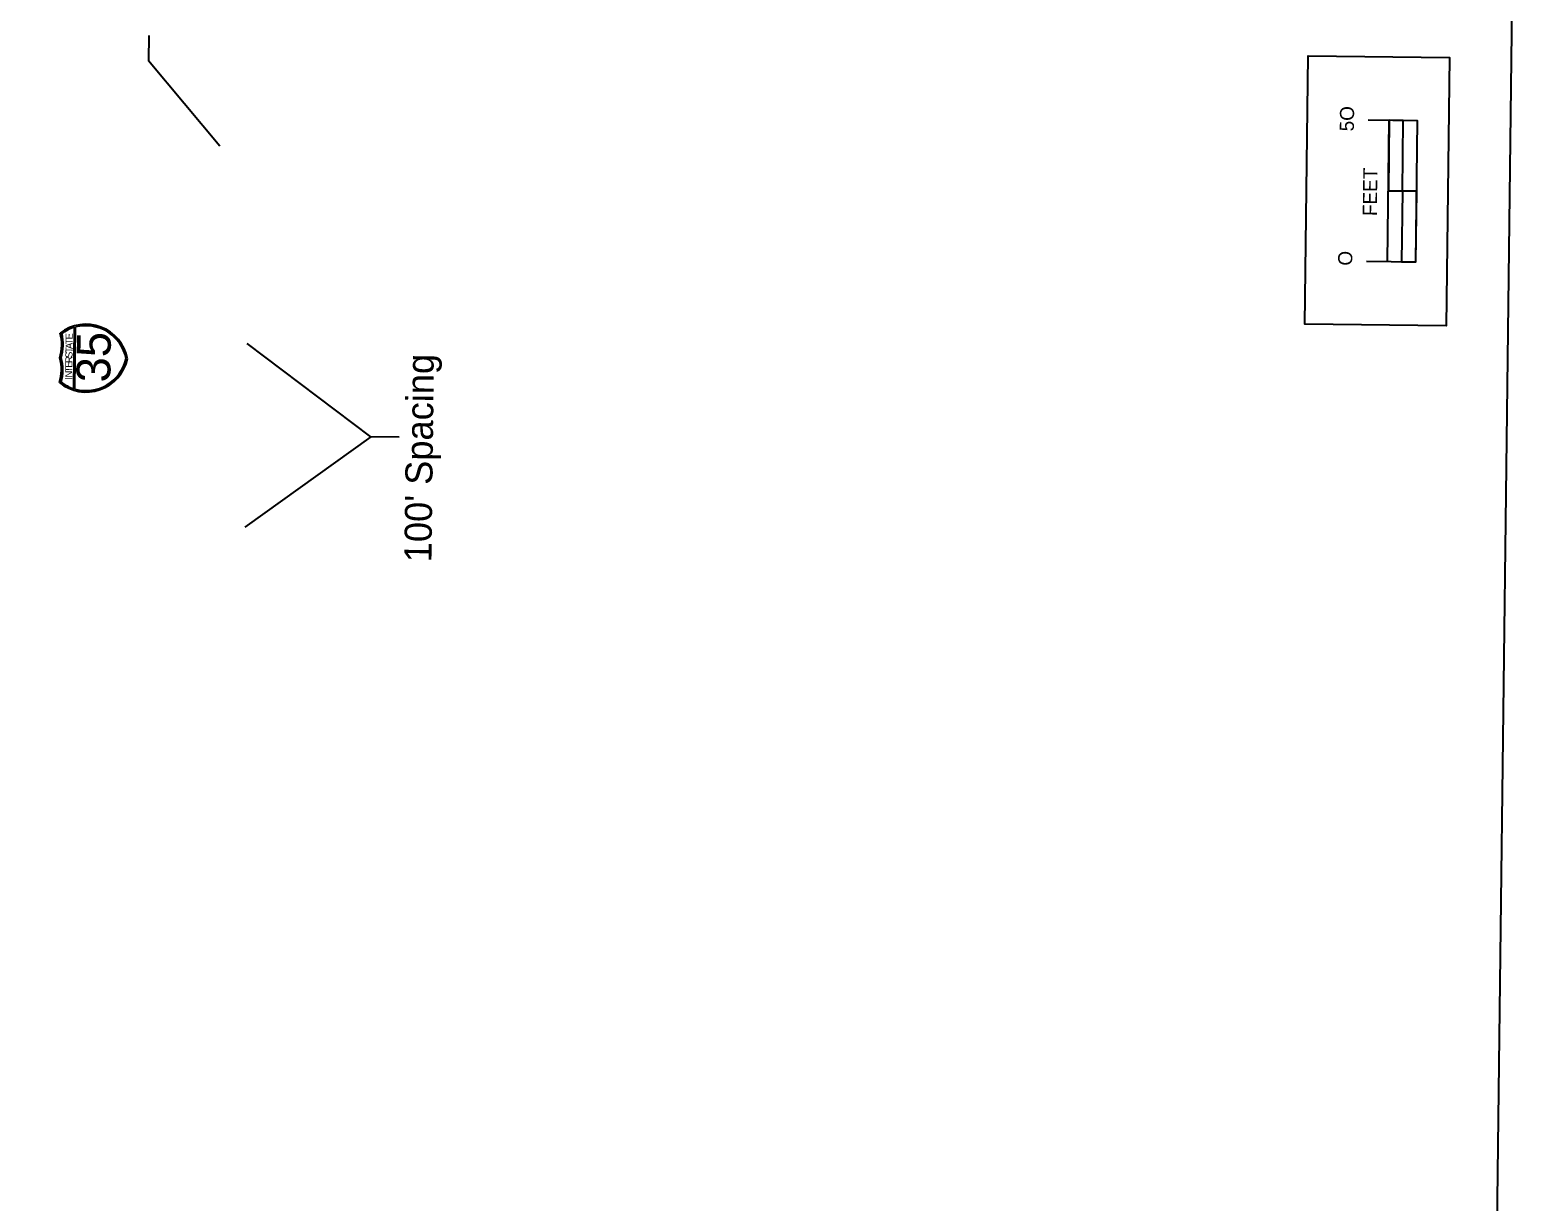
# Model space of a CAD drawing. Extents: x 4959127 to 4960275, y 3872379 to 3884458.
# Drawn here: x 4959631 to 4960164, y 3874282 to 3874697 of the extents above; entities that cross this region are included whole.
import ezdxf

# ---------------------------------------------------------------- set-up
doc = ezdxf.new("R2010")
doc.units = 0
for name, color, linetype in [('dsnCellElements', 7, 'Continuous'), ('dsnCellsHighwaySymbols', 7, 'Continuous'), ('dsnCellsScaleBlock', 7, 'Continuous'), ('NamedBoundary', 7, 'Continuous'), ('SheetText', 7, 'Continuous')]:
    doc.layers.add(name, color=color, linetype=linetype)

msp = doc.modelspace()

# ---------------------------------------------------------------- linework, layer by layer
at = {"layer": 'dsnCellElements'}
msp.add_lwpolyline([(4960081.92, 3874593.12), (4960083.09, 3874688.11), (4960133.08, 3874687.5), (4960131.92, 3874592.51)], close=True, dxfattribs=at)
msp.add_lwpolyline([(4960081.92, 3874593.12), (4960083.09, 3874688.11), (4960133.08, 3874687.5), (4960131.92, 3874592.51)], close=True, dxfattribs=at)
at = {"layer": 'dsnCellsHighwaySymbols'}
for p, q in [((4959646.17, 3874591.92), (4959645.91, 3874570.23)), ((4959646.4, 3874570.08), (4959646.67, 3874592.06))]:
    msp.add_line(p, q, dxfattribs=at)
for centre, radius, start, end in [((4959650.3, 3874578.02), 15, 10.8347, 127.6287), ((4959650.3, 3874578.02), 14.5, 106.5608, 126.3017), ((4959650.31, 3874578.03), 14.5, 11.2271, 104.5442), ((4959626.75, 3874585.7), 15, 342.3065, 16.2887), ((4959626.74, 3874585.73), 15.5, 342.7231, 14.8585), ((4959626.64, 3874576.93), 15, 342.3065, 16.2887), ((4959650.38, 3874584.02), 15, 230.9665, 347.7605), ((4959626.63, 3874576.89), 15.5, 343.7366, 15.8721), ((4959650.39, 3874584.02), 14.5, 254.051, 347.368), ((4959650.38, 3874584.02), 14.5, 232.2935, 252.0342)]:
    msp.add_arc(centre, radius, start, end, dxfattribs=at)
at = {"layer": 'dsnCellsScaleBlock'}
msp.add_line((4960121.5, 3874640.14), (4960111.5, 3874640.26), dxfattribs=at)
msp.add_line((4960121.5, 3874640.14), (4960111.5, 3874640.26), dxfattribs=at)
for points in [[(4960131.92, 3874592.51), (4960081.92, 3874593.12), (4960083.09, 3874688.11), (4960133.08, 3874687.5)], [(4960116.47, 3874640.2), (4960116.77, 3874665.2), (4960111.81, 3874665.26), (4960111.5, 3874640.26)], [(4960121.2, 3874615.14), (4960121.5, 3874640.14), (4960116.47, 3874640.2), (4960116.16, 3874615.2)]]:
    msp.add_lwpolyline(points, close=True, dxfattribs=at)
for points in [[(4960103.7, 3874615.36), (4960121.2, 3874615.14), (4960121.81, 3874665.14), (4960104.31, 3874665.35)], [(4960111.2, 3874615.26), (4960111.81, 3874665.26)]]:
    msp.add_lwpolyline(points, dxfattribs=at)
at = {"layer": 'NamedBoundary'}
msp.add_lwpolyline([(4959145.26, 3873891.33), (4960145.19, 3873879.07), (4960164.4, 3875446.45), (4959164.48, 3875458.71)], close=True, dxfattribs=at)
at = {"layer": 'SheetText'}
for points in [[(4959672.62, 3874695.29), (4959672.51, 3874686.47), (4959697.75, 3874656.2)], [(4959751.14, 3874553.12), (4959751.14, 3874553.12), (4959707.36, 3874586.2)], [(4959761.17, 3874553), (4959751.14, 3874553.12), (4959706.59, 3874521.2)]]:
    msp.add_lwpolyline(points, dxfattribs=at)

# ---------------------------------------------------------------- texts
at = {"layer": 'dsnCellsHighwaySymbols'}
for s, height, p in [('A', 2.5, (4959645.58, 3874584.26)), ('T', 2.5, (4959645.6, 3874585.96)), ('E', 2.5, (4959645.62, 3874587.64)), ('35', 12, (4959658.93, 3874572.39)), ('S', 2.5, (4959645.54, 3874581.08)), ('R', 2.5, (4959645.52, 3874579.29)), ('T', 2.5, (4959645.56, 3874582.87)), ('N', 2.5, (4959645.45, 3874574.16)), ('T', 2.5, (4959645.48, 3874575.94)), ('E', 2.5, (4959645.5, 3874577.62)), ('I', 2.5, (4959645.44, 3874573.28))]:
    msp.add_text(s, height=height, rotation=89.2975, dxfattribs=at).set_placement(p)
at = {"layer": 'dsnCellsScaleBlock'}
for s, p in [('5O', (4960099.26, 3874661.34)), ('FEET', (4960107.39, 3874631.34)), ('O', (4960098.67, 3874613.78))]:
    msp.add_text(s, height=5, rotation=89.2975, dxfattribs=at).set_placement(p)
at = {"layer": 'SheetText'}
msp.add_text("100' Spacing", height=9.6, rotation=89.3042, dxfattribs=at).set_placement((4959772.64, 3874508.68))

doc.saveas('drawing.dxf')
